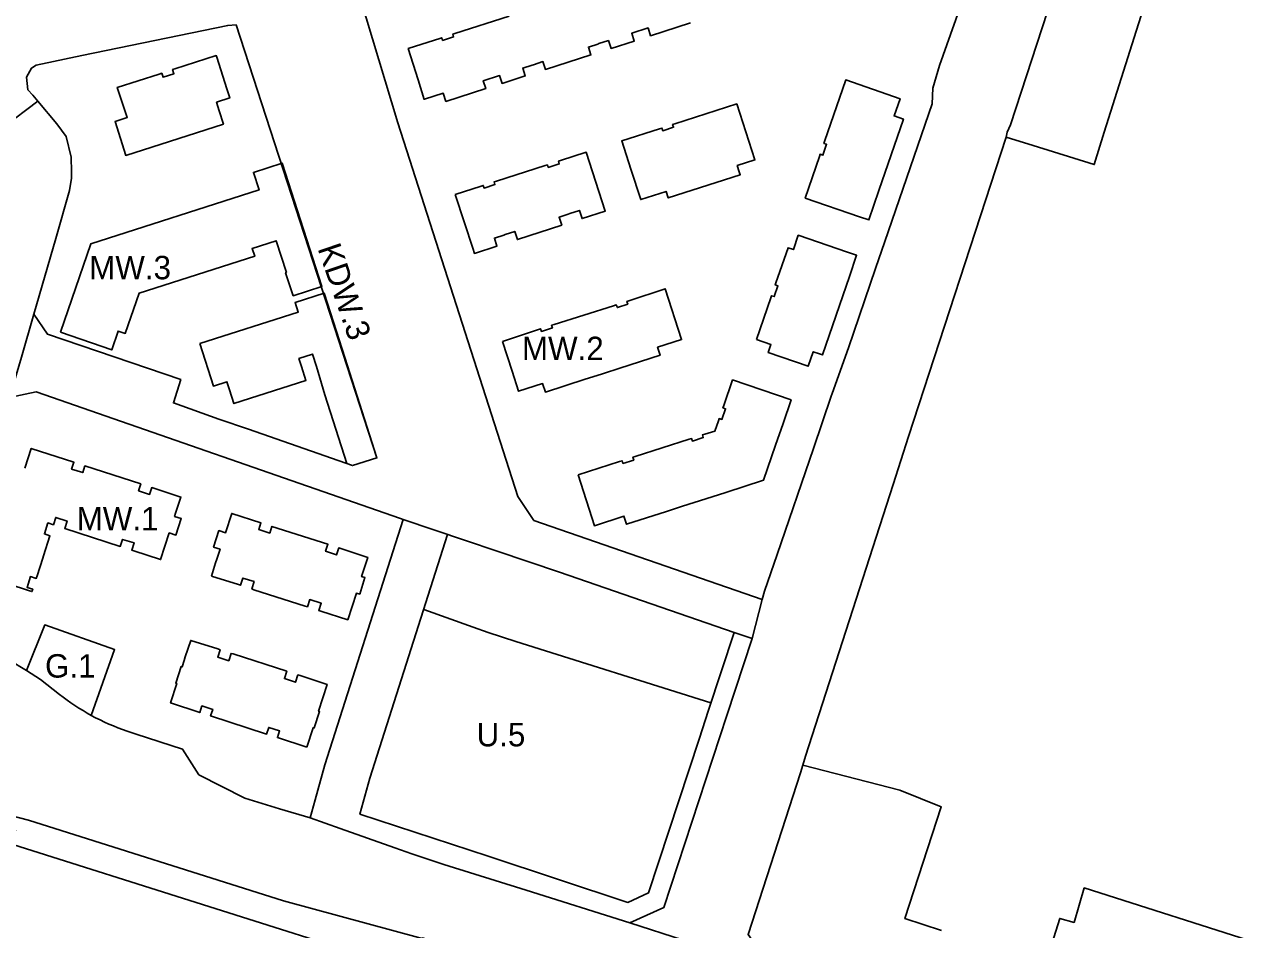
# Model space of a CAD drawing. Extents: x 7416797 to 7419013, y 5549660 to 5551534.
# Drawn here: x 7417614 to 7417878.3, y 5550279.7 to 5550472.8 of the extents above; entities that cross this region are included whole.
import ezdxf

# ---------------------------------------------------------------- set-up
doc = ezdxf.new("R2010")
doc.units = 0
for name, color, linetype in [('LIN_Linia Zabudowy Nieprzekraczalna', 7, 'Continuous'), ('LIN_Linia Zabudowy Obowiązujaca', 7, 'Continuous'), ('LIN_linie_rozgraniczajace', 7, 'Continuous'), ('LIN_nieprzekraczalna_linia_regulacyjna', 7, 'Continuous'), ('TXT_Oznaczenia_przeznaczen', 7, 'Continuous')]:
    doc.layers.add(name, color=color, linetype=linetype)

msp = doc.modelspace()

# ---------------------------------------------------------------- linework, layer by layer
at = {"layer": 'LIN_Linia Zabudowy Nieprzekraczalna'}
for points in [[(7417847.44, 5550509.14), (7417861.79, 5550504.58), (7417859.19, 5550496.4), (7417851.71, 5550472.97), (7417844.38, 5550449.89), (7417842.25, 5550442.95), (7417829.22, 5550447), (7417823.43, 5550448.8), (7417802.63, 5550384.88), (7417799.31, 5550374.64), (7417780.6, 5550316.7), (7417780.05, 5550314.74), (7417800.75, 5550309.44), (7417809.6, 5550305.82), (7417801.84, 5550282), (7417809.66, 5550279.48)], [(7417704.24, 5550364.01), (7417687.64, 5550312), (7417685.51, 5550304.26), (7417712.9, 5550295.32), (7417742.69, 5550285.43), (7417747.14, 5550287.51), (7417757.92, 5550320.28), (7417759.89, 5550326.48), (7417765.39, 5550343.09)], [(7417692.43, 5550272.17), (7417611.45, 5550297.78), (7417611.98, 5550300.89), (7417608.73, 5550301.43), (7417608.96, 5550302.84), (7417604.93, 5550303.53), (7417604.7, 5550302.11), (7417601.39, 5550302.66), (7417601, 5550300.42), (7417594.29, 5550302.09), (7417590.14, 5550298.35), (7417589.15, 5550286.98), (7417595.98, 5550210.57)], [(7417831.83, 5550272.37), (7417834.9, 5550282.03), (7417837.97, 5550281.18), (7417840.12, 5550288.54), (7417878.46, 5550276.31)]]:
    msp.add_lwpolyline(points, dxfattribs=at)
at = {"layer": 'LIN_Linia Zabudowy Obowiązujaca'}
for points in [[(7417717.39, 5550474.63), (7417705.8, 5550470.91), (7417705.31, 5550470.76), (7417705.49, 5550470.2), (7417703.16, 5550469.46), (7417702.98, 5550470.02), (7417702.58, 5550469.88), (7417696.04, 5550467.78), (7417695.82, 5550467.71), (7417697.91, 5550461.08), (7417699.25, 5550456.86), (7417699.33, 5550456.89), (7417703.31, 5550458.17), (7417703.86, 5550456.45), (7417712.36, 5550459.18), (7417711.84, 5550460.84), (7417715.31, 5550461.96), (7417715.84, 5550460.29), (7417720.81, 5550461.88), (7417720.28, 5550463.55), (7417722.31, 5550464.2), (7417722.55, 5550464.28), (7417724.58, 5550464.93), (7417725.11, 5550463.26), (7417734.81, 5550466.36), (7417734.28, 5550468.03), (7417736.31, 5550468.69), (7417736.54, 5550468.77), (7417738.57, 5550469.41), (7417739.11, 5550467.75), (7417744.08, 5550469.33), (7417743.55, 5550471), (7417747.02, 5550472.12), (7417747.55, 5550470.45), (7417756.11, 5550473.19)], [(7417606.02, 5550354.87), (7417614.95, 5550351.97), (7417615.5, 5550351.79), (7417615.67, 5550352.3), (7417614.47, 5550352.7), (7417615.19, 5550355), (7417616.41, 5550354.62), (7417616.6, 5550355.14), (7417617.81, 5550358.91), (7417617.97, 5550359.43), (7417619.35, 5550363.73), (7417618.17, 5550364.11), (7417618.91, 5550366.45), (7417620.1, 5550366.07), (7417620.6, 5550367.63), (7417623.01, 5550366.84), (7417622.5, 5550365.27), (7417634.34, 5550361.44), (7417634.85, 5550362.95), (7417637.31, 5550362.23), (7417636.79, 5550360.66), (7417637.23, 5550360.47), (7417642.97, 5550358.63), (7417644.82, 5550364.34), (7417646.25, 5550363.87), (7417647.38, 5550367.37), (7417646.64, 5550367.61), (7417645.95, 5550367.83), (7417646.18, 5550368.53), (7417647.3, 5550371.99), (7417641.08, 5550374.01), (7417640.61, 5550372.56), (7417638.26, 5550373.33), (7417638.73, 5550374.78), (7417626.81, 5550378.64), (7417626.34, 5550377.19), (7417623.98, 5550377.95), (7417624.45, 5550379.4), (7417615.37, 5550382.35), (7417613.95, 5550378.12)]]:
    msp.add_lwpolyline(points, dxfattribs=at)
for points in [[(7417641.09, 5550446.68), (7417656.39, 5550451.59), (7417655.49, 5550454.42), (7417654.9, 5550456.27), (7417657.72, 5550457.18), (7417657.1, 5550459.12), (7417654.96, 5550465.89), (7417654.85, 5550466.21), (7417645.98, 5550463.37), (7417645.52, 5550463.22), (7417645.8, 5550462.36), (7417643.48, 5550461.6), (7417643.2, 5550462.46), (7417642.65, 5550462.29), (7417633.72, 5550459.44), (7417635.85, 5550452.98), (7417633.25, 5550452.13), (7417635.54, 5550444.91)], [(7417792.14, 5550431.83), (7417794.16, 5550431.14), (7417796.27, 5550437.39), (7417801.52, 5550452.65), (7417799.54, 5550453.33), (7417800.81, 5550457.02), (7417789.22, 5550461.04), (7417784.68, 5550447.89), (7417784.54, 5550447.48), (7417785.13, 5550447.28), (7417784.33, 5550444.95), (7417783.74, 5550445.15), (7417783.59, 5550444.7), (7417780.57, 5550435.79)], [(7417743.34, 5550442.01), (7417745.44, 5550435.48), (7417750.86, 5550437.22), (7417751.31, 5550435.83), (7417766.7, 5550440.78), (7417766.5, 5550441.4), (7417766.07, 5550442.75), (7417769.82, 5550443.96), (7417765.94, 5550455.89), (7417752.76, 5550451.66), (7417752.27, 5550451.5), (7417752.45, 5550450.92), (7417750.16, 5550450.17), (7417749.97, 5550450.76), (7417749.45, 5550450.59), (7417741.41, 5550448.01)], [(7417705.87, 5550436.6), (7417707.86, 5550430.5), (7417709.59, 5550425.09), (7417709.95, 5550423.98), (7417714.76, 5550425.54), (7417714.21, 5550427.25), (7417716.22, 5550427.91), (7417716.55, 5550428.01), (7417718.56, 5550428.69), (7417719.12, 5550426.96), (7417728.58, 5550430.04), (7417728.04, 5550431.72), (7417729.99, 5550432.37), (7417730.32, 5550432.48), (7417732.35, 5550433.17), (7417732.92, 5550431.41), (7417737.89, 5550433.02), (7417733.83, 5550445.57), (7417728.35, 5550443.81), (7417727.87, 5550443.66), (7417728.05, 5550443.1), (7417725.72, 5550442.34), (7417725.54, 5550442.9), (7417725.07, 5550442.76), (7417714.66, 5550439.41), (7417714.15, 5550439.25), (7417714.33, 5550438.68), (7417712, 5550437.93), (7417711.82, 5550438.5), (7417711.36, 5550438.36)], [(7417621.58, 5550407.16), (7417632.52, 5550403.4), (7417633.9, 5550407.42), (7417635.43, 5550406.9), (7417638.38, 5550415.49), (7417663.05, 5550423.39), (7417662.51, 5550425.04), (7417667.66, 5550426.69), (7417669.82, 5550419.93), (7417669.64, 5550419.88), (7417671.27, 5550414.96), (7417677.39, 5550416.92), (7417668.95, 5550443.26), (7417662.79, 5550441.29), (7417663.98, 5550437.55), (7417628.05, 5550426.03)], [(7417770.2, 5550405.59), (7417773.25, 5550404.54), (7417772.66, 5550402.83), (7417781.21, 5550399.9), (7417782.27, 5550402.99), (7417783.63, 5550402.54), (7417784.27, 5550402.33), (7417789.99, 5550419.06), (7417791.53, 5550423.59), (7417789.56, 5550424.27), (7417779.07, 5550427.86), (7417778.03, 5550424.8), (7417776.9, 5550425.19), (7417774.31, 5550417.7), (7417774.16, 5550417.26), (7417774.74, 5550417.07), (7417773.97, 5550414.76), (7417773.39, 5550414.95), (7417773.23, 5550414.48)], [(7417651.35, 5550404.73), (7417654.25, 5550395.68), (7417657.12, 5550396.6), (7417657.66, 5550394.9), (7417658.62, 5550391.94), (7417673.99, 5550396.84), (7417673.02, 5550399.85), (7417672.48, 5550401.55), (7417675.38, 5550402.49), (7417676.22, 5550399.85), (7417678.01, 5550393.83), (7417682.71, 5550379.16), (7417683.92, 5550378.71), (7417689.13, 5550380.33), (7417682.29, 5550401.76), (7417680.51, 5550407.31), (7417677.87, 5550415.54), (7417671.68, 5550413.54), (7417672.36, 5550411.46)], [(7417715.94, 5550405.21), (7417717.99, 5550398.82), (7417719.37, 5550394.55), (7417724.51, 5550396.2), (7417725.09, 5550394.39), (7417733.58, 5550397.14), (7417737.05, 5550398.24), (7417737.52, 5550398.39), (7417741.01, 5550399.51), (7417749.6, 5550402.24), (7417749.05, 5550403.96), (7417754.17, 5550405.6), (7417750.7, 5550416.44), (7417742.93, 5550413.88), (7417742.51, 5550413.75), (7417742.7, 5550413.17), (7417740.46, 5550412.43), (7417740.24, 5550413), (7417739.65, 5550412.81), (7417726.94, 5550408.82), (7417726.43, 5550408.66), (7417726.61, 5550408.08), (7417724.27, 5550407.34), (7417724.09, 5550407.92), (7417723.63, 5550407.77)], [(7417732.07, 5550376.73), (7417735.55, 5550365.86), (7417741.86, 5550367.92), (7417742.42, 5550366.18), (7417750.92, 5550368.91), (7417754.38, 5550370.01), (7417759.34, 5550371.6), (7417763.62, 5550372.97), (7417771.63, 5550375.56), (7417774.21, 5550383.04), (7417775.84, 5550387.71), (7417777.55, 5550392.7), (7417765.06, 5550397), (7417763.18, 5550391.53), (7417763, 5550391.04), (7417763.58, 5550390.84), (7417762.79, 5550388.55), (7417762.22, 5550388.74), (7417762.03, 5550388.23), (7417761.29, 5550386.08), (7417759.12, 5550385.39), (7417758.63, 5550385.24), (7417758.81, 5550384.68), (7417756.49, 5550383.92), (7417756.31, 5550384.48), (7417755.8, 5550384.32), (7417744.28, 5550380.62), (7417743.78, 5550380.47), (7417743.97, 5550379.88), (7417741.65, 5550379.15), (7417741.46, 5550379.72), (7417740.94, 5550379.57)], [(7417653.83, 5550355.12), (7417659.57, 5550353.29), (7417660.02, 5550353.14), (7417660.52, 5550354.7), (7417662.93, 5550353.92), (7417662.44, 5550352.36), (7417662.88, 5550352.21), (7417673.85, 5550348.69), (7417674.3, 5550348.55), (7417674.81, 5550350.11), (7417677.24, 5550349.32), (7417676.74, 5550347.77), (7417677.18, 5550347.62), (7417682.93, 5550345.78), (7417684.76, 5550351.46), (7417685.48, 5550351.26), (7417686.59, 5550354.78), (7417685.87, 5550355.01), (7417687.19, 5550359.11), (7417681.01, 5550361.12), (7417680.53, 5550359.64), (7417678.19, 5550360.4), (7417678.68, 5550361.92), (7417666.73, 5550365.72), (7417666.27, 5550364.28), (7417663.9, 5550365.03), (7417664.38, 5550366.48), (7417658.17, 5550368.48), (7417656.83, 5550364.35), (7417655.4, 5550364.82), (7417654.26, 5550361.31), (7417655.65, 5550360.83), (7417655, 5550358.73), (7417654.71, 5550357.91)], [(7417674.18, 5550318.62), (7417675.52, 5550322.74), (7417675.76, 5550322.69), (7417676.9, 5550326.2), (7417676.68, 5550326.27), (7417678.5, 5550332), (7417672.73, 5550333.86), (7417672.28, 5550334.01), (7417671.77, 5550332.44), (7417669.4, 5550333.22), (7417669.9, 5550334.78), (7417658.49, 5550338.49), (7417658, 5550338.6), (7417657.5, 5550337.05), (7417655.15, 5550337.81), (7417655.65, 5550339.37), (7417655.15, 5550339.57), (7417649.41, 5550341.38), (7417648.23, 5550337.88), (7417648, 5550337.09), (7417647.54, 5550335.71), (7417647.32, 5550335.78), (7417646.2, 5550332.28), (7417646.42, 5550332.21), (7417645.1, 5550328.03), (7417651.31, 5550325.97), (7417651.77, 5550327.41), (7417654.1, 5550326.65), (7417653.65, 5550325.25), (7417665.59, 5550321.39), (7417666.06, 5550322.81), (7417668.37, 5550322.06), (7417667.91, 5550320.64)]]:
    msp.add_lwpolyline(points, close=True, dxfattribs=at)
at = {"layer": 'LIN_linie_rozgraniczajace'}
for p, q in [((7417609.46, 5550450.96), (7417616.73, 5550456.52)), ((7417771.39, 5550350.09), (7417769.26, 5550341.75)), ((7417743.12, 5550281.1), (7417773.52, 5550271.33))]:
    msp.add_line(p, q, dxfattribs=at)
for points in [[(7417873.74, 5550605.53), (7417863.34, 5550573.52), (7417854.43, 5550546.09), (7417846.81, 5550520.04), (7417845.27, 5550514.42), (7417843.62, 5550510.36), (7417824.36, 5550451.41), (7417823.69, 5550449.9), (7417823.43, 5550448.8), (7417802.63, 5550384.88), (7417799.31, 5550374.64), (7417780.6, 5550316.7), (7417780.05, 5550314.74), (7417779.59, 5550313.09), (7417768.36, 5550278.62), (7417773.52, 5550271.33)], [(7417771.39, 5550350.09), (7417771.85, 5550351.92), (7417774.55, 5550359.75), (7417782.3, 5550382.33), (7417786.12, 5550393.5), (7417786.33, 5550394.06), (7417789.82, 5550403.83), (7417795.58, 5550420.74), (7417797.58, 5550426.56), (7417807.67, 5550455.91), (7417807.81, 5550459.25), (7417809.26, 5550464.12), (7417820.13, 5550494.86), (7417823.49, 5550502.87)], [(7417685.5, 5550478.84), (7417693.58, 5550451.86), (7417719.23, 5550372.07), (7417722.66, 5550366.97), (7417771.39, 5550350.09)], [(7417659.07, 5550472.8), (7417657.31, 5550472.67), (7417626.17, 5550466.27), (7417616.39, 5550464.2), (7417615.43, 5550463.54), (7417614.34, 5550461.65), (7417614.64, 5550458.89), (7417615.66, 5550457.8), (7417616.73, 5550456.52)], [(7417659.07, 5550472.8), (7417689.13, 5550380.33), (7417683.92, 5550378.71), (7417661.76, 5550386.5), (7417655.41, 5550388.64), (7417645.71, 5550392.08), (7417647.27, 5550397.04), (7417618.79, 5550406.74), (7417615.9, 5550411)], [(7417616.73, 5550456.52), (7417620.78, 5550451.62), (7417622.81, 5550448.94), (7417623.87, 5550444.56), (7417623.96, 5550441.38), (7417623.97, 5550440.04), (7417623.54, 5550437.42), (7417620.59, 5550427.14), (7417615.9, 5550411)], [(7417615.9, 5550411), (7417613.24, 5550401.85), (7417611.54, 5550396.09), (7417610.69, 5550393.22)], [(7417610.69, 5550393.22), (7417616.37, 5550394.41), (7417694.2, 5550367.39), (7417694.76, 5550367.2)], [(7417694.76, 5550367.2), (7417678.05, 5550314.85), (7417675.99, 5550307.36), (7417674.92, 5550303.48)], [(7417769.26, 5550341.75), (7417765.39, 5550343.09), (7417728.08, 5550355.97), (7417694.76, 5550367.2)], [(7417614.32, 5550334.95), (7417602.94, 5550341.82), (7417597.45, 5550348.99)], [(7417628.17, 5550325.38), (7417633.16, 5550339.42), (7417618.23, 5550344.67), (7417614.32, 5550334.95)], [(7417769.26, 5550341.75), (7417763.83, 5550325.35), (7417750.42, 5550284.38), (7417743.12, 5550281.1)], [(7417621.35, 5550329.86), (7417617.32, 5550333.03), (7417614.32, 5550334.95)], [(7417674.92, 5550303.48), (7417668.31, 5550305.43), (7417660.94, 5550307.71), (7417651.13, 5550312.69), (7417647.67, 5550318.13), (7417637.76, 5550321.33), (7417635.83, 5550321.99)], [(7417584.39, 5550300.76), (7417592.45, 5550308.74), (7417614.79, 5550303.02), (7417669.2, 5550285.81), (7417698.81, 5550277.72), (7417698.86, 5550277.88), (7417701.9, 5550276.88), (7417701.83, 5550276.67), (7417702.02, 5550276.6), (7417739.04, 5550263.72), (7417856.45, 5550226.59)], [(7417743.12, 5550281.1), (7417721.03, 5550288.03), (7417703.41, 5550293.55), (7417696.62, 5550295.8), (7417692.96, 5550297.1), (7417681.29, 5550301.23), (7417674.92, 5550303.48)]]:
    msp.add_lwpolyline(points, dxfattribs=at)
for start, end in [(231.9953, 241.3602), (241.3602, 250.9691)]:
    msp.add_arc((7417652.14, 5550369.26), 50, start, end, dxfattribs=at)
at = {"layer": 'LIN_nieprzekraczalna_linia_regulacyjna'}
msp.add_lwpolyline([(7417760.42, 5550328.07), (7417718.76, 5550341.14), (7417712.86, 5550343.09), (7417709.67, 5550344.23), (7417699.12, 5550347.96)], dxfattribs=at)

# ---------------------------------------------------------------- texts
at = {"layer": 'TXT_Oznaczenia_przeznaczen'}
msp.add_text('KDW.3', height=5, rotation=288.9308, dxfattribs=at).set_placement((7417676.42, 5550425.08))
for s, p in [('MW.3', (7417627.73, 5550418.47)), ('MW.2', (7417720.1, 5550401.21)), ('MW.1', (7417625.05, 5550364.86)), ('G.1', (7417618.3, 5550333.44)), ('U.5', (7417710.42, 5550318.76))]:
    msp.add_text(s, height=5, dxfattribs=at).set_placement(p)

doc.saveas('drawing.dxf')
